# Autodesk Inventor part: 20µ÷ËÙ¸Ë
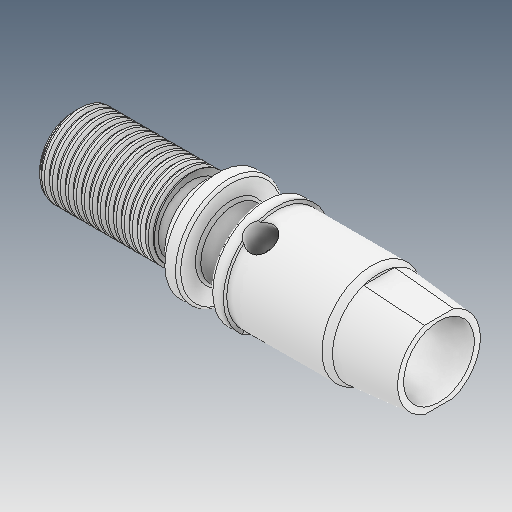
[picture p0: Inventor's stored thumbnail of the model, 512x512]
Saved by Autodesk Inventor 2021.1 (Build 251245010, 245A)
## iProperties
Created: 2021-05
Part Number: 20µ÷ËÙ¸Ë
Material: Ogólny
Document SubType Name: Modeling
Designer: user
Density: 1 g/cm^3
Appearance: Domyślna
Author: user
Revision Number: ÈÎºÎ
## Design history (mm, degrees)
feature "ÊäÈë1"
node "Bryła1"
